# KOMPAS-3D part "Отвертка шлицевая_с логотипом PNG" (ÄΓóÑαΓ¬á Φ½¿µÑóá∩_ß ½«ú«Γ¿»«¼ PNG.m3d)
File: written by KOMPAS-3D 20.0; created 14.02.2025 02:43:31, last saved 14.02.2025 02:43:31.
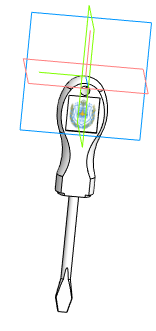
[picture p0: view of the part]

Document properties: Автор: User Windows; Полное имя файла: D:\Работа\ЦДП\2025 г\Отвертка шлицевая_с логотипом PNG.m3d

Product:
- Part/product: Отвертка шлицевая_с логотипом PNG
    Масса: 0.0765532

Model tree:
1. Операция без истории:1
2. Эскиз:1  (with: Операция без истории:1)

Referenced files in C:\Users\Professional\Downloads\BMSTU_Герб\RGB\PNG\: Logo_Color_No-BG.png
